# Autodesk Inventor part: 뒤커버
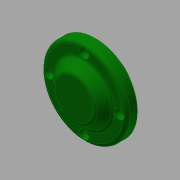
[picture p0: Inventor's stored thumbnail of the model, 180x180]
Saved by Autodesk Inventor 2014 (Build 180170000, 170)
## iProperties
Created: 2017-08
Part Number: 뒤커버
Material: 알루미늄 6061
Document SubType Name: Modeling
Designer: mduedu
Density: 1 g/cm^3
Appearance: 진녹색
Author: mduedu
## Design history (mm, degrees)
sketch "스케치1"
  geometry: C1 r 35 at (0, 0); 1 further point
  constraints: 1 centre point, 1 coincident
  dimensions: "d0" = 70 diameter of C1
extrude "돌출1" new body sketch "스케치1" distance "d1" = 10; taper "d2" = 0 deg
sketch "스케치2"
  geometry: C1 r 24 at (0, 0); 1 further point
  constraints: 1 centre point, 1 coincident
  dimensions: "d3" = 48 diameter of C1
node "작업 평면1"
sketch "스케치3"
  geometry: C1 r 17 at (0, 0); 1 further point
  constraints: 1 centre point, 1 coincident
  dimensions: "d5" = 34 diameter of C1
feature "로프트1" sketch "스케치3" dims "d6" = 0, "d7" = 90 deg, "d8" = 0, "d9" = 90 deg
sketch "스케치4"
  geometry: C1 r 24 at (0, 0) reference; 1 further point
extrude "돌출2" join sketch "스케치4" distance "d10" = 8; taper "d11" = 0 deg
hole "구멍1" diameter "d14" = 40; stored, may be unused: countersink angle "d18" = 90 deg, drill point angle "d20" = 0 deg; dims "d12" = 10, "d13" = 10, "d15" = 6, "d16" = 4, "d17" = 2, "d19" = 12
hole "구멍2" diameter "d23" = 34; stored, may be unused: countersink angle "d27" = 90 deg, drill point angle "d29" = 0 deg; dims "d24" = 6, "d25" = 4, "d26" = 2, "d28" = 6, "d62" = 10, "d63" = 10
chamfer "모따기1" distance "d39" = 1; stored, may be unused: second distance "d40" = 2, angle "d41" = 45 deg
fillet "모깎기1" dims "d42" = 0.3
fillet "모깎기2" dims "d43" = 3
sketch "스케치5" dims "d44" = 58
  geometry: 6 further points
  constraints: 2 vertical alignment, 1 coincident, 7 other
  dimensions: "d47" = 360 deg dimension on point (0, 0) point (0, 29) (derived)
sketch "스케치6"
  geometry: 4 further points
  constraints: 4 other
hole "구멍4" sketch "스케치6" at (0, 29), (-29, 0), (29, 0), (0, -29) diameter "d49" = 4.5; stored, may be unused: countersink angle "d53" = 90 deg, drill point angle "d55" = 0 deg; dims "d50" = 6, "d51" = 8, "d52" = 4.6, "d54" = 8
fillet "모깎기3" dims "d56" = 3
fillet "모깎기4" dims "d57" = 3
fillet "모깎기5" dims "d58" = 3
chamfer "모따기2" distance "d59" = 1; stored, may be unused: second distance "d60" = 2, angle "d61" = 45 deg
node "솔리드1"
other parameters: "d4" = 8
